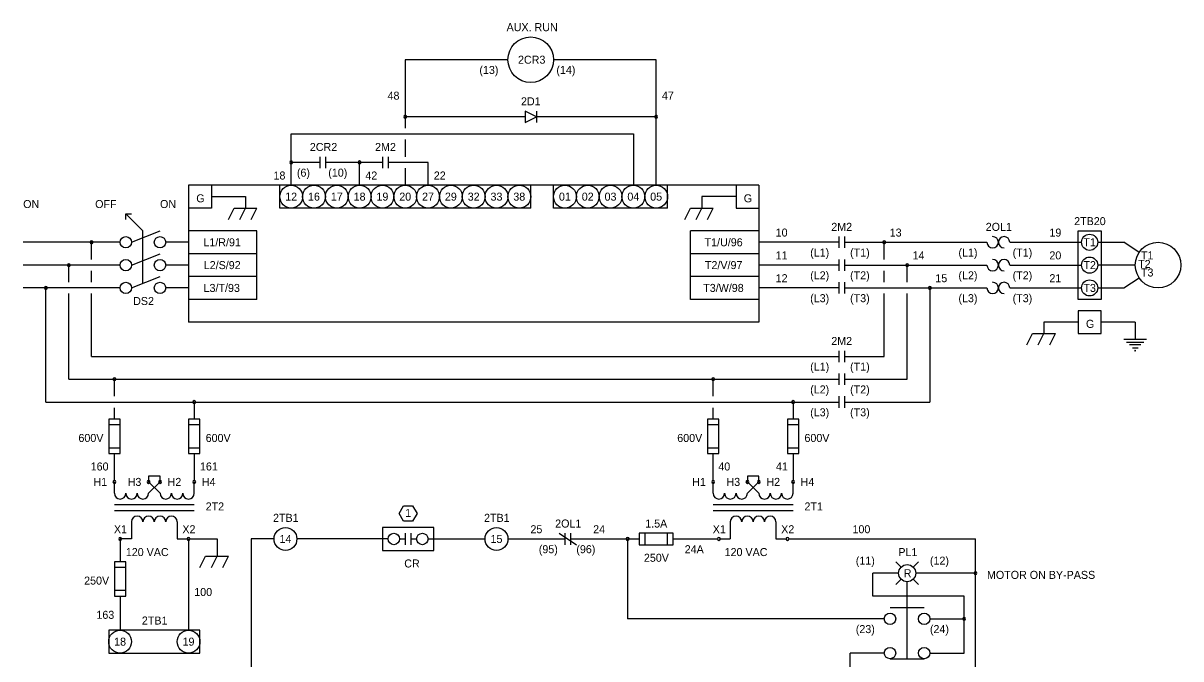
# Model space of a CAD drawing. Extents: x 10338 to 10578, y 10012 to 10165.
# Drawn here: x 10481.8 to 10578.2, y 10111.7 to 10164.7 of the extents above; entities that cross this region are included whole.
import ezdxf

# ---------------------------------------------------------------- set-up
doc = ezdxf.new("R2010")
doc.units = 0
for name, color, linetype in [('Level 60', 7, 'Continuous'), ('Level 61', 7, 'Continuous'), ('Level 62', 7, 'Continuous'), ('Level 63', 7, 'Continuous')]:
    doc.layers.add(name, color=color, linetype=linetype)

# ---------------------------------------------------------------- blocks, each defined once
blk = doc.blocks.new('PL0')
at = {"layer": 'Level 63'}
for p, q in [((-0.0055, 0.0055), (-0.0104, 0.0104)), ((0.0055, 0.0055), (0.0104, 0.0104)), ((-0.0055, -0.0055), (-0.0104, -0.0104)), ((0.0055, -0.0055), (0.0104, -0.0104))]:
    blk.add_line(p, q, dxfattribs=at)
blk.add_circle((0, 0), 0.00781, dxfattribs=at)

msp = doc.modelspace()

# ---------------------------------------------------------------- linework, layer by layer
at = {"layer": 'Level 60'}
msp.add_lwpolyline([(10514.574, 10123.838), (10514.202, 10123.193), (10513.457, 10123.193), (10513.084, 10123.838), (10513.457, 10124.483), (10514.202, 10124.483)], close=True, dxfattribs=at)
at = {"layer": 'Level 61'}
for p, q in [((10522.142, 10161.615), (10513.592, 10161.615)), ((10513.592, 10161.615), (10513.592, 10155.915)), ((10534.492, 10161.615), (10525.942, 10161.615)), ((10534.492, 10151.165), (10534.492, 10161.615)), ((10523.567, 10156.865), (10513.592, 10156.865)), ((10534.492, 10156.865), (10524.517, 10156.865)), ((10504.092, 10155.44), (10532.592, 10155.44)), ((10504.092, 10151.165), (10504.092, 10155.44)), ((10513.592, 10154.965), (10513.592, 10153.54)), ((10532.592, 10155.44), (10532.592, 10151.165)), ((10506.467, 10153.065), (10504.092, 10153.065)), ((10511.692, 10153.065), (10506.942, 10153.065)), ((10509.792, 10151.165), (10509.792, 10153.065)), ((10515.492, 10153.065), (10512.167, 10153.065)), ((10513.592, 10152.59), (10513.592, 10151.165)), ((10515.492, 10151.165), (10515.492, 10153.065)), ((10524.042, 10149.265), (10524.042, 10151.165)), ((10525.942, 10149.265), (10525.942, 10151.165)), ((10535.442, 10149.265), (10535.442, 10151.165)), ((10497.442, 10150.215), (10500.292, 10150.215)), ((10500.292, 10150.215), (10500.292, 10149.265)), ((10541.142, 10150.215), (10538.292, 10150.215)), ((10538.292, 10150.215), (10538.292, 10149.265)), ((10535.442, 10149.265), (10525.942, 10149.265)), ((10491.742, 10142.995), (10491.742, 10147.365)), ((10489.842, 10146.415), (10481.767, 10146.415)), ((10487.467, 10144.99), (10487.467, 10146.415)), ((10495.542, 10146.415), (10493.642, 10146.415)), ((10549.692, 10146.415), (10543.042, 10146.415)), ((10550.167, 10146.415), (10562.042, 10146.415)), ((10553.492, 10144.99), (10553.492, 10146.415)), ((10563.942, 10146.415), (10569.879, 10146.415)), ((10571.304, 10146.415), (10573.442, 10146.415)), ((10574.711, 10145.569), (10573.442, 10146.415)), ((10489.842, 10144.515), (10481.767, 10144.515)), ((10485.567, 10143.09), (10485.567, 10144.515)), ((10487.467, 10143.09), (10487.467, 10144.04)), ((10495.542, 10144.515), (10493.642, 10144.515)), ((10549.692, 10144.515), (10543.042, 10144.515)), ((10550.167, 10144.515), (10562.042, 10144.515)), ((10553.492, 10143.09), (10553.492, 10144.04)), ((10555.392, 10143.09), (10555.392, 10144.515)), ((10563.942, 10144.515), (10569.879, 10144.515)), ((10574.392, 10144.515), (10571.304, 10144.515)), ((10573.442, 10142.615), (10574.711, 10143.461)), ((10489.842, 10142.615), (10481.767, 10142.615)), ((10483.667, 10133.115), (10483.667, 10142.615)), ((10485.567, 10135.015), (10485.567, 10142.14)), ((10487.467, 10136.915), (10487.467, 10142.14)), ((10495.542, 10142.615), (10493.642, 10142.615)), ((10549.692, 10142.615), (10543.042, 10142.615)), ((10550.167, 10142.615), (10562.042, 10142.615)), ((10553.492, 10136.915), (10553.492, 10142.14)), ((10555.392, 10135.015), (10555.392, 10142.14)), ((10557.292, 10142.615), (10557.292, 10133.115)), ((10563.942, 10142.615), (10569.879, 10142.615)), ((10571.304, 10142.615), (10573.442, 10142.615)), ((10569.642, 10139.765), (10566.792, 10139.765)), ((10566.792, 10139.765), (10566.792, 10138.815)), ((10574.392, 10139.765), (10571.542, 10139.765)), ((10574.392, 10139.765), (10574.392, 10138.34)), ((10487.467, 10136.915), (10549.692, 10136.915)), ((10550.167, 10136.915), (10553.492, 10136.915)), ((10485.567, 10135.015), (10549.692, 10135.015)), ((10489.367, 10133.59), (10489.367, 10135.015)), ((10539.242, 10133.59), (10539.242, 10135.015)), ((10550.167, 10135.015), (10555.392, 10135.015)), ((10483.667, 10133.115), (10549.692, 10133.115)), ((10489.367, 10131.69), (10489.367, 10132.64)), ((10496.017, 10133.115), (10496.017, 10131.69)), ((10539.242, 10131.69), (10539.242, 10132.64)), ((10545.892, 10133.115), (10545.892, 10131.69)), ((10550.167, 10133.115), (10557.292, 10133.115)), ((10489.842, 10131.215), (10488.892, 10131.215)), ((10496.492, 10131.215), (10495.542, 10131.215)), ((10539.717, 10131.215), (10538.767, 10131.215)), ((10546.367, 10131.215), (10545.417, 10131.215)), ((10488.892, 10129.315), (10489.842, 10129.315)), ((10489.367, 10126.584), (10489.367, 10128.84)), ((10495.542, 10129.315), (10496.492, 10129.315)), ((10496.017, 10128.84), (10496.017, 10126.584)), ((10538.767, 10129.315), (10539.717, 10129.315)), ((10539.242, 10126.584), (10539.242, 10128.84)), ((10545.417, 10129.315), (10546.367, 10129.315)), ((10545.892, 10128.84), (10545.892, 10126.584)), ((10493.167, 10126.94), (10492.217, 10126.94)), ((10492.217, 10126.94), (10492.217, 10126.465)), ((10493.167, 10126.465), (10493.167, 10126.94)), ((10542.092, 10126.94), (10542.092, 10126.465)), ((10543.042, 10126.94), (10542.092, 10126.94)), ((10543.042, 10126.465), (10543.042, 10126.94)), ((10515.967, 10122.665), (10511.692, 10122.665)), ((10511.692, 10122.665), (10511.692, 10120.765)), ((10515.967, 10120.765), (10515.967, 10122.665)), ((10526.417, 10122.19), (10527.842, 10121.24)), ((10533.542, 10122.19), (10533.542, 10121.24)), ((10535.442, 10121.24), (10535.442, 10122.19)), ((10489.842, 10121.715), (10489.842, 10119.815)), ((10495.542, 10121.715), (10495.542, 10114.115)), ((10495.661, 10121.715), (10497.917, 10121.715)), ((10497.917, 10121.715), (10497.917, 10120.29)), ((10500.767, 10121.715), (10500.767, 10102.715)), ((10502.667, 10121.715), (10500.767, 10121.715)), ((10512.167, 10121.715), (10504.567, 10121.715)), ((10515.492, 10121.715), (10520.242, 10121.715)), ((10522.142, 10121.715), (10526.892, 10121.715)), ((10527.367, 10121.715), (10533.067, 10121.715)), ((10532.117, 10121.715), (10532.117, 10115.065)), ((10535.917, 10121.715), (10539.598, 10121.715)), ((10545.536, 10121.715), (10561.092, 10121.715)), ((10561.092, 10079.915), (10561.092, 10121.715)), ((10511.692, 10120.765), (10515.967, 10120.765)), ((10490.317, 10119.34), (10489.367, 10119.34)), ((10554.679, 10118.865), (10552.542, 10118.865)), ((10552.542, 10116.965), (10552.542, 10118.865)), ((10561.092, 10118.865), (10556.104, 10118.865)), ((10555.392, 10111.74), (10555.392, 10118.153)), ((10489.367, 10117.44), (10490.317, 10117.44)), ((10489.842, 10116.965), (10489.842, 10114.115)), ((10560.142, 10116.965), (10552.542, 10116.965)), ((10560.142, 10112.215), (10560.142, 10116.965)), ((10553.492, 10115.065), (10532.117, 10115.065)), ((10557.292, 10115.065), (10560.142, 10115.065)), ((10550.642, 10106.515), (10550.642, 10112.215)), ((10553.492, 10112.215), (10550.642, 10112.215)), ((10557.292, 10112.215), (10560.142, 10112.215))]:
    msp.add_line(p, q, dxfattribs=at)
for centre, radius in [((10504.092, 10150.215), 0.95), ((10505.992, 10150.215), 0.95), ((10507.892, 10150.215), 0.95), ((10509.792, 10150.215), 0.95), ((10511.692, 10150.215), 0.95), ((10513.592, 10150.215), 0.95), ((10515.492, 10150.215), 0.95), ((10517.392, 10150.215), 0.95), ((10519.292, 10150.215), 0.95), ((10521.192, 10150.215), 0.95), ((10523.092, 10150.215), 0.95), ((10526.892, 10150.215), 0.95), ((10528.792, 10150.215), 0.95), ((10530.692, 10150.215), 0.95), ((10532.592, 10150.215), 0.95), ((10534.492, 10150.215), 0.95), ((10570.592, 10146.415), 0.672), ((10570.592, 10144.515), 0.672), ((10570.592, 10142.615), 0.672), ((10489.842, 10113.165), 0.95), ((10495.542, 10113.165), 0.95)]:
    msp.add_circle(centre, radius, dxfattribs=at)
for centre, start, end in [((10513.592, 10156.865), 0, 180), ((10513.592, 10156.865), 180, 0), ((10534.492, 10156.865), 0, 180), ((10534.492, 10156.865), 180, 0), ((10504.092, 10153.065), 0, 180), ((10504.092, 10153.065), 180, 0), ((10509.792, 10153.065), 0, 180), ((10509.792, 10153.065), 180, 0), ((10487.467, 10146.415), 0, 180), ((10487.467, 10146.415), 180, 0), ((10553.492, 10146.415), 0, 180), ((10553.492, 10146.415), 180, 0), ((10485.567, 10144.515), 0, 180), ((10485.567, 10144.515), 180, 0), ((10555.392, 10144.515), 0, 180), ((10555.392, 10144.515), 180, 0), ((10483.667, 10142.615), 0, 180), ((10483.667, 10142.615), 180, 0), ((10557.292, 10142.615), 0, 180), ((10557.292, 10142.615), 180, 0), ((10489.367, 10135.015), 0, 180), ((10489.367, 10135.015), 180, 0), ((10539.242, 10135.015), 0, 180), ((10539.242, 10135.015), 180, 0), ((10496.017, 10133.115), 0, 180), ((10496.017, 10133.115), 180, 0), ((10545.892, 10133.115), 0, 180), ((10545.892, 10133.115), 180, 0), ((10532.117, 10121.715), 0, 180), ((10532.117, 10121.715), 180, 0), ((10561.092, 10118.865), 0, 180), ((10561.092, 10118.865), 180, 0), ((10560.142, 10115.065), 0, 180), ((10560.142, 10115.065), 180, 0)]:
    msp.add_arc(centre, 0.119, start, end, dxfattribs=at)
at = {"layer": 'Level 62'}
for p, q in [((10524.517, 10156.865), (10523.567, 10157.34)), ((10523.567, 10157.34), (10523.567, 10156.39)), ((10523.567, 10156.39), (10524.517, 10156.865)), ((10524.517, 10157.34), (10524.517, 10156.39)), ((10506.467, 10153.54), (10506.467, 10152.59)), ((10506.942, 10153.54), (10506.942, 10152.59)), ((10511.692, 10153.54), (10511.692, 10152.59)), ((10512.167, 10153.54), (10512.167, 10152.59)), ((10495.542, 10151.165), (10495.542, 10139.765)), ((10543.042, 10151.165), (10495.542, 10151.165)), ((10497.442, 10151.165), (10497.442, 10149.265)), ((10503.142, 10149.265), (10503.142, 10151.165)), ((10541.142, 10151.165), (10541.142, 10149.265)), ((10543.042, 10151.165), (10543.042, 10139.765)), ((10490.317, 10148.315), (10490.317, 10148.79)), ((10491.742, 10147.365), (10490.317, 10148.79)), ((10490.317, 10148.79), (10490.792, 10148.79)), ((10497.442, 10149.265), (10495.542, 10149.265)), ((10498.867, 10148.315), (10499.342, 10149.265)), ((10499.342, 10149.265), (10501.242, 10149.265)), ((10499.817, 10148.315), (10500.292, 10149.265)), ((10500.767, 10148.315), (10501.242, 10149.265)), ((10524.042, 10149.265), (10503.142, 10149.265)), ((10536.867, 10148.315), (10537.342, 10149.265)), ((10537.342, 10149.265), (10539.242, 10149.265)), ((10537.817, 10148.315), (10538.292, 10149.265)), ((10538.767, 10148.315), (10539.242, 10149.265)), ((10541.142, 10149.265), (10543.042, 10149.265)), ((10490.792, 10146.415), (10493.167, 10147.365)), ((10501.242, 10147.365), (10495.542, 10147.365)), ((10501.242, 10141.665), (10501.242, 10147.365)), ((10543.042, 10147.365), (10537.342, 10147.365)), ((10537.342, 10141.665), (10537.342, 10147.365)), ((10549.692, 10146.89), (10549.692, 10145.94)), ((10550.167, 10146.89), (10550.167, 10145.94)), ((10569.642, 10141.665), (10569.642, 10147.365)), ((10569.642, 10147.365), (10571.542, 10147.365)), ((10571.542, 10147.365), (10571.542, 10141.665)), ((10490.792, 10144.515), (10493.167, 10145.465)), ((10501.242, 10145.465), (10495.542, 10145.465)), ((10543.042, 10145.465), (10537.342, 10145.465)), ((10549.692, 10144.99), (10549.692, 10144.04)), ((10550.167, 10144.99), (10550.167, 10144.04)), ((10490.792, 10142.615), (10493.167, 10143.565)), ((10501.242, 10143.565), (10495.542, 10143.565)), ((10543.042, 10143.565), (10537.342, 10143.565)), ((10549.692, 10143.09), (10549.692, 10142.14)), ((10550.167, 10143.09), (10550.167, 10142.14)), ((10501.242, 10141.665), (10495.542, 10141.665)), ((10543.042, 10141.665), (10537.342, 10141.665)), ((10571.542, 10141.665), (10569.642, 10141.665)), ((10571.542, 10140.715), (10569.642, 10140.715)), ((10569.642, 10140.715), (10569.642, 10138.815)), ((10571.542, 10138.815), (10571.542, 10140.715)), ((10543.042, 10139.765), (10495.542, 10139.765)), ((10565.367, 10137.865), (10565.842, 10138.815)), ((10565.842, 10138.815), (10567.742, 10138.815)), ((10566.317, 10137.865), (10566.792, 10138.815)), ((10567.267, 10137.865), (10567.742, 10138.815)), ((10569.642, 10138.815), (10571.542, 10138.815)), ((10573.442, 10138.34), (10575.342, 10138.34)), ((10549.692, 10137.39), (10549.692, 10136.44)), ((10550.167, 10137.39), (10550.167, 10136.44)), ((10573.679, 10138.103), (10575.104, 10138.103)), ((10574.867, 10137.865), (10573.917, 10137.865)), ((10574.154, 10137.628), (10574.629, 10137.628)), ((10549.692, 10135.49), (10549.692, 10134.54)), ((10550.167, 10135.49), (10550.167, 10134.54)), ((10549.692, 10133.59), (10549.692, 10132.64)), ((10550.167, 10133.59), (10550.167, 10132.64)), ((10488.892, 10131.69), (10488.892, 10128.84)), ((10489.842, 10131.69), (10488.892, 10131.69)), ((10489.842, 10128.84), (10489.842, 10131.69)), ((10495.542, 10131.69), (10495.542, 10128.84)), ((10496.492, 10131.69), (10495.542, 10131.69)), ((10496.492, 10128.84), (10496.492, 10131.69)), ((10539.717, 10131.69), (10538.767, 10131.69)), ((10538.767, 10131.69), (10538.767, 10128.84)), ((10539.717, 10128.84), (10539.717, 10131.69)), ((10545.417, 10131.69), (10545.417, 10128.84)), ((10546.367, 10131.69), (10545.417, 10131.69)), ((10546.367, 10128.84), (10546.367, 10131.69)), ((10488.892, 10128.84), (10489.842, 10128.84)), ((10495.542, 10128.84), (10496.492, 10128.84)), ((10538.767, 10128.84), (10539.717, 10128.84)), ((10545.417, 10128.84), (10546.367, 10128.84)), ((10489.367, 10125.515), (10489.367, 10126.465)), ((10492.217, 10125.515), (10493.167, 10126.465)), ((10492.217, 10126.465), (10493.167, 10125.515)), ((10496.017, 10125.515), (10496.017, 10126.465)), ((10539.242, 10125.515), (10539.242, 10126.465)), ((10542.092, 10126.465), (10543.042, 10125.515)), ((10542.092, 10125.515), (10543.042, 10126.465)), ((10545.892, 10125.515), (10545.892, 10126.465)), ((10496.017, 10124.565), (10489.367, 10124.565)), ((10489.367, 10124.09), (10496.017, 10124.09)), ((10545.892, 10124.565), (10539.242, 10124.565)), ((10539.242, 10124.09), (10545.892, 10124.09)), ((10490.792, 10123.14), (10490.792, 10121.715)), ((10494.592, 10123.14), (10494.592, 10121.715)), ((10540.667, 10123.14), (10540.667, 10121.715)), ((10544.467, 10123.14), (10544.467, 10121.715)), ((10513.592, 10122.19), (10513.592, 10121.24)), ((10514.067, 10122.19), (10514.067, 10121.24)), ((10526.892, 10122.19), (10526.892, 10121.24)), ((10527.367, 10122.19), (10527.367, 10121.24)), ((10535.917, 10122.19), (10533.067, 10122.19)), ((10533.067, 10122.19), (10533.067, 10121.24)), ((10535.917, 10121.24), (10535.917, 10122.19)), ((10490.792, 10121.715), (10489.842, 10121.715)), ((10494.592, 10121.715), (10495.519, 10121.715)), ((10513.117, 10121.715), (10513.592, 10121.715)), ((10514.067, 10121.715), (10514.542, 10121.715)), ((10533.067, 10121.24), (10535.917, 10121.24)), ((10539.819, 10121.715), (10540.667, 10121.715)), ((10544.467, 10121.715), (10545.274, 10121.715)), ((10489.367, 10119.815), (10489.367, 10116.965)), ((10490.317, 10119.815), (10489.367, 10119.815)), ((10490.317, 10116.965), (10490.317, 10119.815)), ((10496.492, 10119.34), (10496.967, 10120.29)), ((10496.967, 10120.29), (10498.867, 10120.29)), ((10497.442, 10119.34), (10497.917, 10120.29)), ((10498.392, 10119.34), (10498.867, 10120.29)), ((10489.367, 10116.965), (10490.317, 10116.965)), ((10553.967, 10116.015), (10556.817, 10116.015)), ((10496.492, 10114.115), (10488.892, 10114.115)), ((10488.892, 10114.115), (10488.892, 10112.215)), ((10496.492, 10112.215), (10496.492, 10114.115)), ((10488.892, 10112.215), (10496.492, 10112.215)), ((10553.967, 10111.74), (10556.817, 10111.74))]:
    msp.add_line(p, q, dxfattribs=at)
for centre, radius in [((10524.042, 10161.615), 1.9), ((10490.317, 10146.415), 0.475), ((10493.167, 10146.415), 0.475), ((10576.292, 10144.515), 1.9), ((10490.317, 10144.515), 0.475), ((10493.167, 10144.515), 0.475), ((10490.317, 10142.615), 0.475), ((10493.167, 10142.615), 0.475), ((10503.617, 10121.715), 0.95), ((10512.642, 10121.715), 0.475), ((10515.017, 10121.715), 0.475), ((10521.192, 10121.715), 0.95), ((10553.967, 10115.065), 0.475), ((10556.817, 10115.065), 0.475), ((10553.967, 10112.215), 0.475), ((10556.817, 10112.215), 0.475)]:
    msp.add_circle(centre, radius, dxfattribs=at)
for centre, radius, start, end in [((10562.517, 10146.415), 0.475, 180, 90), ((10563.467, 10146.415), 0.475, 0, 270), ((10562.517, 10144.515), 0.475, 180, 90), ((10563.467, 10144.515), 0.475, 0, 270), ((10562.517, 10142.615), 0.475, 180, 90), ((10563.467, 10142.615), 0.475, 0, 270), ((10574.392, 10137.39), 0.0297, 0, 180), ((10574.392, 10137.39), 0.0297, 180, 0), ((10489.367, 10126.465), 0.119, 90, 270), ((10489.367, 10126.465), 0.119, 270, 90), ((10492.217, 10126.465), 0.119, 90, 270), ((10492.217, 10126.465), 0.119, 270, 90), ((10493.167, 10126.465), 0.119, 90, 270), ((10493.167, 10126.465), 0.119, 270, 90), ((10496.017, 10126.465), 0.119, 90, 270), ((10496.017, 10126.465), 0.119, 270, 90), ((10539.242, 10126.465), 0.119, 90, 270), ((10539.242, 10126.465), 0.119, 270, 90), ((10542.092, 10126.465), 0.119, 90, 270), ((10542.092, 10126.465), 0.119, 270, 90), ((10543.042, 10126.465), 0.119, 90, 270), ((10543.042, 10126.465), 0.119, 270, 90), ((10545.892, 10126.465), 0.119, 90, 270), ((10545.892, 10126.465), 0.119, 270, 90), ((10489.842, 10125.515), 0.475, 180, 0), ((10490.792, 10125.515), 0.475, 180, 0), ((10491.742, 10125.515), 0.475, 180, 0), ((10493.642, 10125.515), 0.475, 180, 0), ((10494.592, 10125.515), 0.475, 180, 0), ((10495.542, 10125.515), 0.475, 180, 0), ((10539.717, 10125.515), 0.475, 180, 0), ((10540.667, 10125.515), 0.475, 180, 0), ((10541.617, 10125.515), 0.475, 180, 0), ((10543.517, 10125.515), 0.475, 180, 0), ((10544.467, 10125.515), 0.475, 180, 0), ((10545.417, 10125.515), 0.475, 180, 0), ((10491.267, 10123.14), 0.475, 0, 180), ((10492.217, 10123.14), 0.475, 0, 180), ((10493.167, 10123.14), 0.475, 0, 180), ((10494.117, 10123.14), 0.475, 0, 180), ((10541.142, 10123.14), 0.475, 0, 180), ((10542.092, 10123.14), 0.475, 0, 180), ((10543.042, 10123.14), 0.475, 0, 180), ((10543.992, 10123.14), 0.475, 0, 180), ((10489.842, 10121.715), 0.119, 0, 180), ((10495.542, 10121.715), 0.119, 0, 180), ((10539.717, 10121.715), 0.119, 0, 180), ((10545.417, 10121.715), 0.119, 0, 180), ((10489.842, 10121.715), 0.119, 180, 0), ((10495.542, 10121.715), 0.119, 180, 0), ((10539.717, 10121.715), 0.119, 180, 0), ((10545.417, 10121.715), 0.119, 180, 0)]:
    msp.add_arc(centre, radius, start, end, dxfattribs=at)

# ---------------------------------------------------------------- block references
at = {"layer": 'Level 62', "xscale": 91.19999999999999, "yscale": 91.2}
msp.add_blockref('PL0', (10555.393, 10118.866), dxfattribs=at)

# ---------------------------------------------------------------- texts
at = {"layer": 'Level 60'}
msp.add_text('1', height=0.667, dxfattribs=at).set_placement((10513.585, 10123.545))
at = {"layer": 'Level 63'}
for s, height, p in [('AUX. RUN', 0.6667, (10522.031, 10163.991)), ('2CR3', 0.6667, (10522.984, 10161.282)), ('(13)', 0.6667, (10519.768, 10160.428)), ('(14)', 0.6667, (10526.181, 10160.428)), ('48', 0.6667, (10512.118, 10158.291)), ('2D1', 0.6667, (10523.232, 10157.816)), ('47', 0.6667, (10534.968, 10158.291)), ('2CR2', 0.6667, (10505.647, 10154.016)), ('2M2', 0.6667, (10511.077, 10154.016)), ('18', 0.6667, (10502.618, 10151.641)), ('(6)', 0.6667, (10504.568, 10151.878)), ('(10)', 0.6667, (10507.181, 10151.878)), ('42', 0.6667, (10510.268, 10151.641)), ('22', 0.6667, (10515.968, 10151.641)), ('ON', 0.6667, (10481.768, 10149.266)), ('OFF', 0.6667, (10487.764, 10149.266)), ('ON', 0.6667, (10493.168, 10149.266)), ('G', 0.667, (10496.187, 10149.741)), ('12', 0.6667, (10503.594, 10149.882)), ('16', 0.6667, (10505.493, 10149.882)), ('17', 0.6667, (10507.394, 10149.882)), ('18', 0.6667, (10509.294, 10149.882)), ('19', 0.6667, (10511.194, 10149.882)), ('20', 0.6667, (10513.093, 10149.882)), ('27', 0.6667, (10514.994, 10149.882)), ('29', 0.6667, (10516.894, 10149.882)), ('32', 0.6667, (10518.794, 10149.882)), ('33', 0.6667, (10520.694, 10149.882)), ('38', 0.6667, (10522.594, 10149.882)), ('01', 0.6667, (10526.393, 10149.882)), ('02', 0.6667, (10528.294, 10149.882)), ('03', 0.6667, (10530.194, 10149.882)), ('04', 0.6667, (10532.094, 10149.882)), ('05', 0.6667, (10533.994, 10149.882)), ('G', 0.667, (10541.787, 10149.741)), ('2M2', 0.6667, (10549.077, 10147.366)), ('2OL1', 0.6667, (10561.94, 10147.366)), ('2TB20', 0.6667, (10569.305, 10147.841)), ('10', 0.6667, (10544.443, 10146.891)), ('13', 0.6667, (10553.944, 10146.891)), ('19', 0.6667, (10567.244, 10146.891)), ('L1/R/91', 0.6667, (10496.78, 10146.082)), ('T1/U/96', 0.6667, (10538.524, 10146.082)), ('(L1)', 0.6667, (10547.318, 10145.228)), ('(T1)', 0.6667, (10550.643, 10145.228)), ('(L1)', 0.6667, (10559.668, 10145.228)), ('(T1)', 0.6667, (10564.181, 10145.228)), ('T1', 0.6667, (10570.075, 10146.082)), ('L2/S/92', 0.6667, (10496.809, 10144.182)), ('T2/V/97', 0.6667, (10538.551, 10144.182)), ('11', 0.6667, (10544.443, 10144.991)), ('14', 0.6667, (10555.844, 10144.991)), ('20', 0.6667, (10567.243, 10144.991)), ('T2', 0.6667, (10574.631, 10144.278)), ('T1', 0.6667, (10574.868, 10144.991)), ('(L2)', 0.6667, (10547.318, 10143.328)), ('(T2)', 0.6667, (10550.643, 10143.328)), ('(L2)', 0.6667, (10559.668, 10143.328)), ('(T2)', 0.6667, (10564.181, 10143.328)), ('T2', 0.6667, (10570.076, 10144.182)), ('T3', 0.6667, (10574.868, 10143.566)), ('L3/T/93', 0.6667, (10496.796, 10142.282)), ('T3/W/98', 0.6667, (10538.411, 10142.282)), ('12', 0.6667, (10544.444, 10143.091)), ('15', 0.6667, (10557.744, 10143.091)), ('21', 0.6667, (10567.243, 10143.091)), ('T3', 0.6667, (10570.076, 10142.282)), ('(L3)', 0.6667, (10547.318, 10141.428)), ('(T3)', 0.6667, (10550.643, 10141.428)), ('(L3)', 0.6667, (10559.668, 10141.428)), ('(T3)', 0.6667, (10564.181, 10141.428)), ('DS2', 0.6667, (10490.927, 10141.191)), ('G', 0.667, (10570.287, 10139.291)), ('2M2', 0.6667, (10549.077, 10137.866)), ('(L1)', 0.6667, (10547.318, 10135.728)), ('(T1)', 0.6667, (10550.643, 10135.728)), ('(L2)', 0.6667, (10547.318, 10133.828)), ('(T2)', 0.6667, (10550.643, 10133.828)), ('(L3)', 0.6667, (10547.318, 10131.928)), ('(T3)', 0.6667, (10550.643, 10131.928)), ('600V', 0.6667, (10486.371, 10129.791)), ('600V', 0.6667, (10496.968, 10129.791)), ('600V', 0.6667, (10536.246, 10129.791)), ('600V', 0.6667, (10546.843, 10129.791)), ('160', 0.6667, (10487.392, 10127.416)), ('161', 0.6667, (10496.493, 10127.416)), ('40', 0.6667, (10539.668, 10127.416)), ('41', 0.6667, (10544.468, 10127.416)), ('H1', 0.6667, (10487.621, 10126.132)), ('H3', 0.6667, (10490.472, 10126.132)), ('H2', 0.6667, (10493.797, 10126.132)), ('H4', 0.6667, (10496.647, 10126.132)), ('H1', 0.6667, (10537.496, 10126.132)), ('H3', 0.6667, (10540.347, 10126.132)), ('H2', 0.6667, (10543.672, 10126.132)), ('H4', 0.6667, (10546.522, 10126.132)), ('2T2', 0.6667, (10496.968, 10124.091)), ('2T1', 0.6667, (10546.843, 10124.091)), ('2TB1', 0.6667, (10502.58, 10123.141)), ('2TB1', 0.6667, (10520.155, 10123.141)), ('X1', 0.6667, (10489.327, 10122.191)), ('X2', 0.6667, (10495.028, 10122.191)), ('25', 0.6667, (10524.019, 10122.191)), ('2OL1', 0.6667, (10526.078, 10122.666)), ('24', 0.6667, (10529.244, 10122.191)), ('1.5A', 0.6667, (10533.579, 10122.666)), ('X1', 0.6667, (10539.202, 10122.191)), ('X2', 0.6667, (10544.903, 10122.191)), ('100', 0.6667, (10550.843, 10122.191)), ('14', 0.6667, (10503.119, 10121.382)), ('15', 0.6667, (10520.694, 10121.382)), ('120 VAC', 0.6667, (10490.318, 10120.291)), ('(95)', 0.6667, (10524.715, 10120.528)), ('(96)', 0.6667, (10527.843, 10120.528)), ('24A', 0.6667, (10536.868, 10120.528)), ('120 VAC', 0.6667, (10540.193, 10120.291)), ('PL1', 0.6667, (10554.662, 10120.291)), ('CR', 0.6667, (10513.509, 10119.341)), ('250V', 0.6667, (10533.469, 10119.816)), ('(11)', 0.6667, (10551.118, 10119.578)), ('(12)', 0.6667, (10557.293, 10119.578)), ('R', 0.667, (10555.109, 10118.532)), ('MOTOR ON BY-PASS', 0.66667, (10562.043, 10118.391)), ('250V', 0.6667, (10486.846, 10117.916)), ('100', 0.6667, (10496.018, 10116.966)), ('163', 0.6667, (10487.868, 10115.066)), ('2TB1', 0.6667, (10491.655, 10114.591)), ('(23)', 0.6667, (10551.118, 10113.878)), ('(24)', 0.6667, (10557.293, 10113.878)), ('18', 0.6667, (10489.344, 10112.832)), ('19', 0.6667, (10495.044, 10112.832))]:
    msp.add_text(s, height=height, dxfattribs=at).set_placement(p)

doc.saveas('drawing.dxf')
